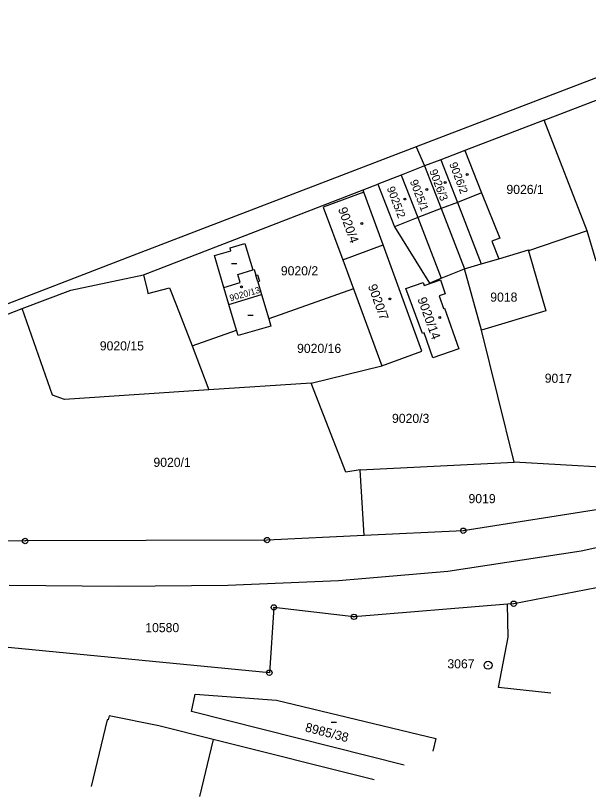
# Model space of a CAD drawing. Extents: x -825057 to -819383, y -1071633 to -1067888.
# Drawn here: x -824872.6 to -824765.8, y -1070119.8 to -1069974.2 of the extents above; entities that cross this region are included whole.
import ezdxf

# ---------------------------------------------------------------- set-up
doc = ezdxf.new("R2010")
doc.units = 0
for name, color, linetype in [('Vrstva 1', 7, 'Continuous'), ('Vrstva 10', 7, 'Continuous'), ('Vrstva 13', 7, 'Continuous'), ('Vrstva 17', 7, 'Continuous'), ('Vrstva 18', 7, 'Continuous'), ('Vrstva 19', 7, 'Continuous'), ('Vrstva 24', 7, 'Continuous'), ('Vrstva 25', 7, 'Continuous'), ('Vrstva 4', 7, 'Continuous')]:
    doc.layers.add(name, color=color, linetype=linetype)

msp = doc.modelspace()

# ---------------------------------------------------------------- linework, layer by layer
at = {"layer": 'Vrstva 1'}
for p, q in [((-824774.05, -1069993.7), (-824762.85, -1069989.42)), ((-824774.05, -1069993.7), (-824788.8, -1069999.36)), ((-824766.03, -1070014.31), (-824774.05, -1069993.7)), ((-824797.89, -1069998.69), (-824796.32, -1070002.24)), ((-824788.8, -1069999.36), (-824793.32, -1070001.09)), ((-824788.8, -1069999.36), (-824785.69, -1070007.27)), ((-824796.32, -1070002.24), (-824800.69, -1070003.94)), ((-824793.32, -1070001.09), (-824796.32, -1070002.24)), ((-824796.32, -1070002.24), (-824793.22, -1070010.18)), ((-824793.32, -1070001.09), (-824790.22, -1070009.02)), ((-824800.69, -1070003.94), (-824805.06, -1070005.63)), ((-824800.69, -1070003.94), (-824797.59, -1070011.87)), ((-824848.71, -1070022.55), (-824807.8, -1070006.69)), ((-824807.8, -1070006.69), (-824805.06, -1070005.63)), ((-824807.64, -1070007.12), (-824807.8, -1070006.69)), ((-824805.06, -1070005.63), (-824801.96, -1070013.56)), ((-824807.64, -1070007.12), (-824815.21, -1070009.92)), ((-824804.04, -1070016.96), (-824807.64, -1070007.12)), ((-824785.69, -1070007.27), (-824782.32, -1070015.7)), ((-824790.22, -1070009.02), (-824785.79, -1070020.49)), ((-824815.21, -1070009.92), (-824811.58, -1070019.76)), ((-824793.22, -1070010.18), (-824788.88, -1070021.4)), ((-824797.59, -1070011.87), (-824793.22, -1070023.18)), ((-824801.96, -1070013.56), (-824795.39, -1070024.07)), ((-824766.03, -1070014.31), (-824776.94, -1070018.05)), ((-824764.34, -1070019.98), (-824766.03, -1070014.31)), ((-824832.58, -1070017.53), (-824829.82, -1070016.71)), ((-824829.82, -1070016.71), (-824828.35, -1070021.64)), ((-824811.58, -1070019.76), (-824804.04, -1070016.96)), ((-824796.81, -1070036.76), (-824804.04, -1070016.96)), ((-824782.32, -1070015.7), (-824783.77, -1070016.27)), ((-824783.77, -1070016.27), (-824782.5, -1070019.53)), ((-824835.49, -1070018.96), (-824832.42, -1070018.04)), ((-824832.42, -1070018.04), (-824832.58, -1070017.53)), ((-824782.5, -1070019.53), (-824776.98, -1070017.91)), ((-824776.98, -1070017.91), (-824776.94, -1070018.05)), ((-824776.94, -1070018.05), (-824773.7, -1070029.26)), ((-824833.74, -1070024.91), (-824835.49, -1070018.96)), ((-824811.58, -1070019.76), (-824809.59, -1070025.17)), ((-824785.79, -1070020.49), (-824782.5, -1070019.53)), ((-824793.22, -1070023.18), (-824788.88, -1070021.4)), ((-824788.88, -1070021.4), (-824785.79, -1070020.49)), ((-824785.74, -1070032.85), (-824788.88, -1070021.4)), ((-824862.29, -1070025.38), (-824848.71, -1070022.55)), ((-824848.71, -1070022.55), (-824848, -1070025.6)), ((-824828.35, -1070021.64), (-824828.07, -1070021.55)), ((-824828.07, -1070021.55), (-824827.76, -1070022.59)), ((-824827.76, -1070022.59), (-824827.5, -1070022.52)), ((-824827.5, -1070022.52), (-824827.12, -1070023.75)), ((-824827.12, -1070023.75), (-824827.4, -1070023.82)), ((-824827.4, -1070023.82), (-824826.71, -1070026.2)), ((-824799.8, -1070025.09), (-824796.57, -1070023.97)), ((-824796.57, -1070023.97), (-824796.38, -1070024.53)), ((-824796.38, -1070024.53), (-824793.39, -1070023.49)), ((-824795.39, -1070024.07), (-824793.22, -1070023.18)), ((-824793.39, -1070023.49), (-824792.49, -1070026.06)), ((-824871.35, -1070028.8), (-824862.29, -1070025.38)), ((-824848, -1070025.6), (-824847.89, -1070026.03)), ((-824847.89, -1070026.03), (-824843.85, -1070024.96)), ((-824843.85, -1070024.96), (-824842.57, -1070028.28)), ((-824832.81, -1070028.06), (-824833.74, -1070024.91)), ((-824809.59, -1070025.17), (-824825.38, -1070030.75)), ((-824809.59, -1070025.17), (-824804.3, -1070039.52)), ((-824796.73, -1070033.49), (-824799.8, -1070025.09)), ((-824826.71, -1070026.2), (-824825.38, -1070030.75)), ((-824792.49, -1070026.06), (-824793.61, -1070026.45)), ((-824793.61, -1070026.45), (-824792.79, -1070028.82)), ((-824842.57, -1070028.28), (-824839.67, -1070035.81)), ((-824831.39, -1070032.88), (-824832.81, -1070028.06)), ((-824865.67, -1070045), (-824871.35, -1070028.8)), ((-824792.79, -1070028.82), (-824792.6, -1070028.76)), ((-824792.6, -1070028.76), (-824789.96, -1070036.37)), ((-824773.7, -1070029.26), (-824785.74, -1070032.85)), ((-824825.38, -1070030.75), (-824824.98, -1070032.1)), ((-824839.67, -1070035.81), (-824831.39, -1070032.88)), ((-824831.09, -1070033.89), (-824831.39, -1070032.88)), ((-824824.98, -1070032.1), (-824831.09, -1070033.89)), ((-824779.63, -1070057.48), (-824785.74, -1070032.85)), ((-824796.42, -1070033.38), (-824796.73, -1070033.49)), ((-824794.8, -1070038.05), (-824796.42, -1070033.38)), ((-824839.67, -1070035.81), (-824836.51, -1070044.01)), ((-824804.3, -1070039.52), (-824796.81, -1070036.76)), ((-824789.96, -1070036.37), (-824794.8, -1070038.05)), ((-824817.48, -1070042.74), (-824804.3, -1070039.52)), ((-824817.48, -1070042.74), (-824836.51, -1070044.01)), ((-824810.99, -1070059.33), (-824817.48, -1070042.74)), ((-824836.51, -1070044.01), (-824863.45, -1070045.81)), ((-824863.45, -1070045.81), (-824865.67, -1070045)), ((-824808.31, -1070058.93), (-824779.63, -1070057.48)), ((-824755.27, -1070058.9), (-824779.63, -1070057.48)), ((-824808.31, -1070058.93), (-824810.99, -1070059.33)), ((-824807.6, -1070071.15), (-824808.31, -1070058.93)), ((-824761.64, -1070065.93), (-824789.12, -1070070.28)), ((-824789.12, -1070070.28), (-824807.6, -1070071.15)), ((-824870.78, -1070072.19), (-824877.18, -1070072.24)), ((-824825.68, -1070072.01), (-824870.78, -1070072.19)), ((-824807.6, -1070071.15), (-824825.68, -1070072.01)), ((-824760.54, -1070080.23), (-824779.72, -1070083.89)), ((-824780.85, -1070083.98), (-824809.49, -1070086.34)), ((-824779.72, -1070083.89), (-824780.85, -1070083.98)), ((-824780.76, -1070090.12), (-824780.85, -1070083.98)), ((-824824.42, -1070084.58), (-824825.26, -1070096.77)), ((-824809.49, -1070086.34), (-824824.42, -1070084.58)), ((-824782.56, -1070099.55), (-824780.76, -1070090.12)), ((-824825.26, -1070096.77), (-824875.24, -1070091.93)), ((-824772.8, -1070100.58), (-824782.56, -1070099.55)), ((-824839.76, -1070104.01), (-824839.11, -1070100.77)), ((-824839.11, -1070100.77), (-824823.93, -1070101.91)), ((-824823.93, -1070101.91), (-824794.25, -1070109.06)), ((-824800.13, -1070113.98), (-824839.76, -1070104.01)), ((-824835.75, -1070109.22), (-824838.31, -1070119.83)), ((-824805.75, -1070116.73), (-824835.75, -1070109.22)), ((-824794.25, -1070109.06), (-824794.8, -1070111.37))]:
    msp.add_line(p, q, dxfattribs=at)
at = {"layer": 'Vrstva 10'}
for p, q in [((-824741.93, -1070068.34), (-824767.15, -1070074.09)), ((-824767.15, -1070074.09), (-824792, -1070077.9)), ((-824792, -1070077.9), (-824812.39, -1070079.65)), ((-824812.39, -1070079.65), (-824833.02, -1070080.49)), ((-824853.34, -1070080.66), (-824873.75, -1070080.47)), ((-824833.02, -1070080.49), (-824853.34, -1070080.66))]:
    msp.add_line(p, q, dxfattribs=at)
at = {"layer": 'Vrstva 13'}
for p, q in [((-824734.26, -1069974.19), (-824797.89, -1069998.69)), ((-824797.89, -1069998.69), (-824850.82, -1070018.98)), ((-824850.82, -1070018.98), (-824879.92, -1070030.25))]:
    msp.add_line(p, q, dxfattribs=at)
at = {"layer": 'Vrstva 24'}
for centre, radius in [((-824789.12, -1070070.28), 0.5), ((-824789.12, -1070070.28), 0.0327), ((-824870.78, -1070072.19), 0.5), ((-824870.78, -1070072.19), 0.0327), ((-824825.68, -1070072.01), 0.5), ((-824825.68, -1070072.01), 0.0327), ((-824779.72, -1070083.89), 0.5), ((-824779.72, -1070083.89), 0.0327), ((-824824.42, -1070084.58), 0.5), ((-824824.42, -1070084.58), 0.0327), ((-824809.49, -1070086.34), 0.5), ((-824809.49, -1070086.34), 0.0327), ((-824784.49, -1070095.37), 0.75), ((-824784.49, -1070095.37), 0.0327), ((-824825.26, -1070096.77), 0.5), ((-824825.26, -1070096.77), 0.0327)]:
    msp.add_circle(centre, radius, dxfattribs=at)
at = {"layer": 'Vrstva 25'}
for p, q in [((-824832.34, -1070020.41), (-824831.34, -1070020.41)), ((-824829.29, -1070030.05), (-824828.29, -1070030.05)), ((-824813.75, -1070105.98), (-824812.75, -1070105.98))]:
    msp.add_line(p, q, dxfattribs=at)
for centre in [(-824788.39, -1070003.81), (-824792.48, -1070005.32), (-824795.92, -1070006.63), (-824800.01, -1070008.4), (-824808.03, -1070012.97), (-824830.48, -1070024.77), (-824802.79, -1070027.05), (-824793.51, -1070030.51)]:
    msp.add_circle(centre, 0.175, dxfattribs=at)
at = {"layer": 'Vrstva 4'}
for p, q in [((-824785.69, -1070007.27), (-824790.22, -1070009.02)), ((-824790.22, -1070009.02), (-824793.22, -1070010.18)), ((-824793.22, -1070010.18), (-824797.59, -1070011.87)), ((-824797.59, -1070011.87), (-824801.96, -1070013.56)), ((-824831.12, -1070022.48), (-824828.35, -1070021.64)), ((-824830.67, -1070023.99), (-824831.12, -1070022.48)), ((-824827.4, -1070023.82), (-824827.76, -1070022.59)), ((-824833.74, -1070024.91), (-824830.67, -1070023.99)), ((-824832.81, -1070028.06), (-824826.71, -1070026.2)), ((-824879.6, -1070032.03), (-824871.35, -1070028.8)), ((-824855.49, -1070105.53), (-824858.5, -1070117.99)), ((-824855.29, -1070105.58), (-824855.49, -1070105.53)), ((-824855.1, -1070104.79), (-824855.29, -1070105.58)), ((-824845.87, -1070106.68), (-824855.1, -1070104.79)), ((-824835.75, -1070109.22), (-824845.87, -1070106.68))]:
    msp.add_line(p, q, dxfattribs=at)

# ---------------------------------------------------------------- texts
at = {"layer": 'Vrstva 17'}
msp.add_text('3067', height=1.7, dxfattribs=at).set_placement((-824792.074, -1070095.95))
at = {"layer": 'Vrstva 18'}
for s, p in [('9020/2', (-824823.114, -1070022.64)), ('9018', (-824784.086, -1070027.55)), ('9020/15', (-824856.86, -1070036.64)), ('9020/16', (-824820.09, -1070037.11)), ('9020/3', (-824802.396, -1070050.17)), ('9020/1', (-824846.862, -1070058.36)), ('9019', (-824788.139, -1070065.14)), ('10580', (-824848.386, -1070089.2))]:
    msp.add_text(s, height=1.7, dxfattribs=at).set_placement(p)
msp.add_text('9017', height=1.7, rotation=359.1, dxfattribs=at).set_placement((-824773.944, -1070042.658))
at = {"layer": 'Vrstva 19'}
for s, height, rotation, p in [('9026/2', 1.5, 290.7, (-824791.758, -1070001.857)), ('9026/3', 1.5, 290.7, (-824795.471, -1070003.17)), ('9025/1', 1.5, 290.7, (-824799.096, -1070005.104)), ('9025/2', 1.5, 290.7, (-824803.388, -1070006.381)), ('9020/4', 1.7, 289.8, (-824812.48, -1070010.262)), ('9020/7', 1.7, 289.8, (-824806.918, -1070024.626)), ('9020/13', 1.2, 16.2, (-824832.48, -1070027.49)), ('9020/14', 1.7, 289.8, (-824797.682, -1070027.049)), ('8985/38', 1.7, 345.6, (-824818.709, -1070107.689))]:
    msp.add_text(s, height=height, rotation=rotation, dxfattribs=at).set_placement(p)
msp.add_text('9026/1', height=1.7, dxfattribs=at).set_placement((-824781.069, -1070007.46))

doc.saveas('drawing.dxf')
